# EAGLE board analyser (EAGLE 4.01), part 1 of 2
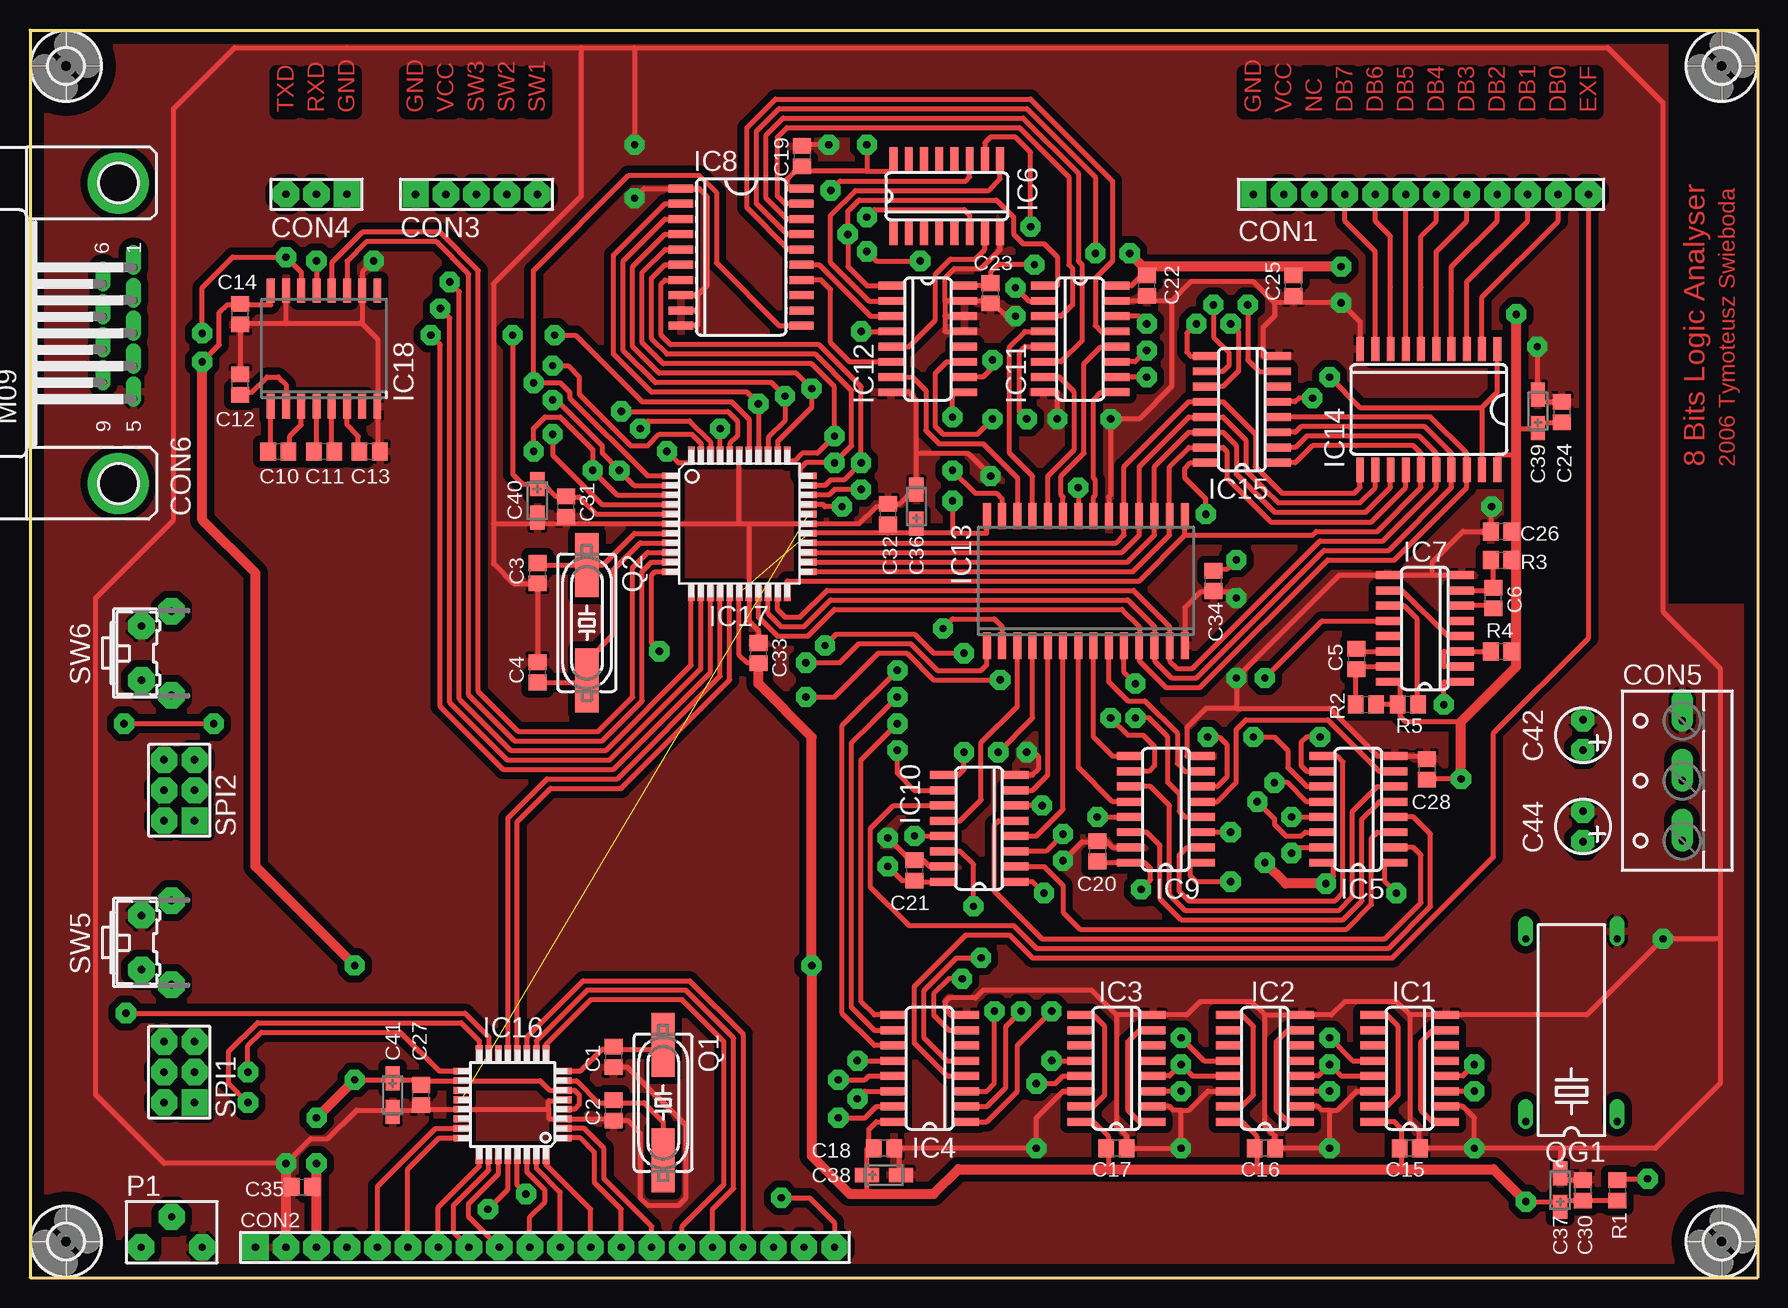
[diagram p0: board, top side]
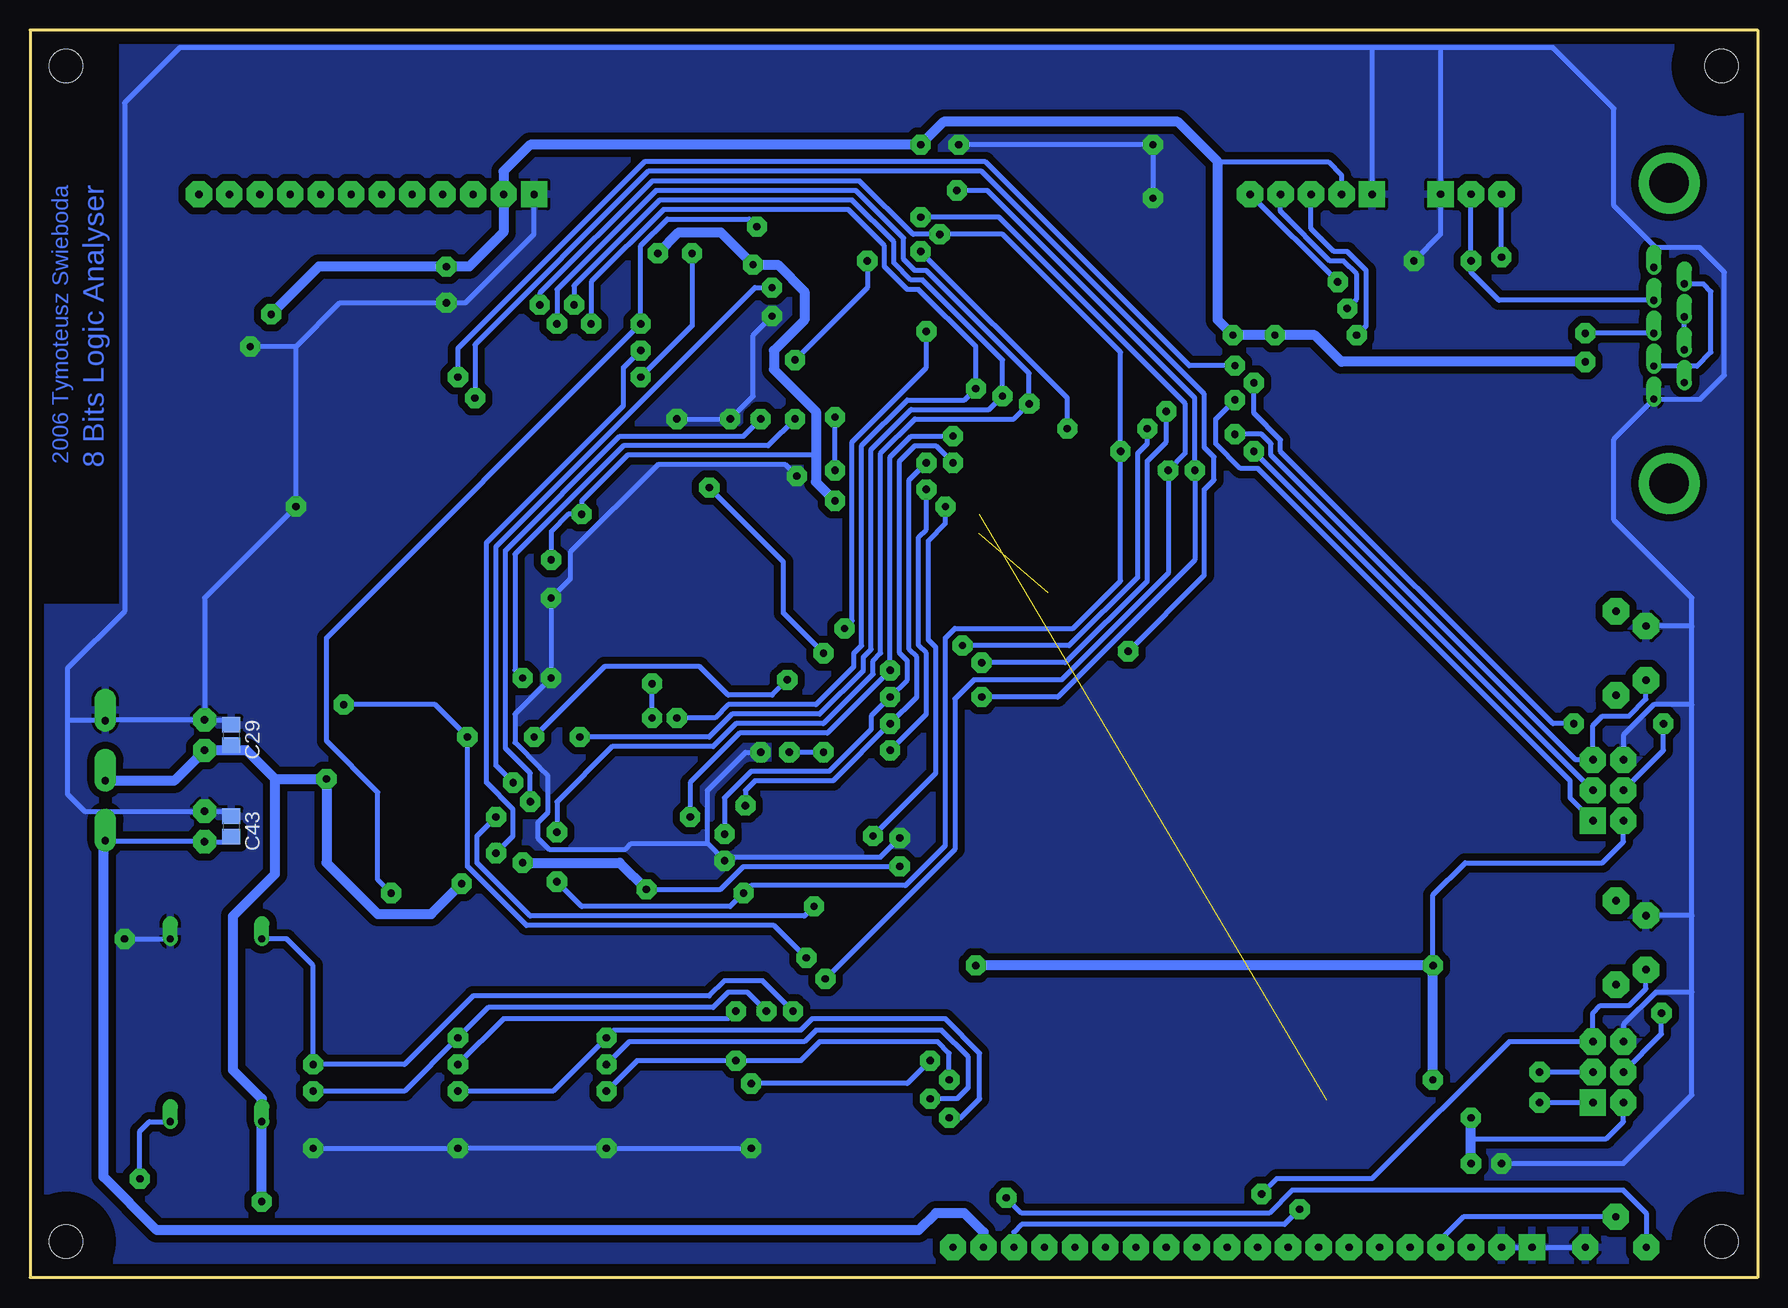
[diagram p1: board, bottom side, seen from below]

Size 144 x 104 mm. Coordinates in mm from the lower left corner, seen from the top.
Outline: 0,0 144,0 144,104 0,104 0,0
Copper layers used: Top, Bottom

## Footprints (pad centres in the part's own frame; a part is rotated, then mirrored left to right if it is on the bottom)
0805 = smd 1.3 x 1.5: 1 -0.85,0; 2 0.85,0
3216 = smd 2 x 1.2: + -1.4,0; - 1.4,0
02P100RA = drill 0.61 pad 1.93 octagon: N -1.27,0; P 1.27,0
CON12X1 = drill 0.61 pad 2.184 square: 1 0,0 | drill 0.61 pad 2.184 octagon: 2 2.54,0; 3 5.08,0; 4 7.62,0; 5 10.16,0; 6 12.7,0; 7 15.24,0; 8 17.78,0; 9 20.32,0; 10 22.86,0; 11 25.4,0; 12 27.94,0
CON20X1 = drill 0.61 pad 2.184 square: 1 0,0 | drill 0.61 pad 2.184 octagon: 2 2.54,0; 3 5.08,0; 4 7.62,0; 5 10.16,0; 6 12.7,0; 7 15.24,0; 8 17.78,0; 9 20.32,0; 10 22.86,0; 11 25.4,0; 12 27.94,0; 13 30.48,0; 14 33.02,0; 15 35.56,0; 16 38.1,0; 17 40.64,0; 18 43.18,0; 19 45.72,0; 20 48.26,0
CON05X1 = drill 0.61 pad 2.184 square: 1 0,0 | drill 0.61 pad 2.184 octagon: 2 2.54,0; 3 5.08,0; 4 7.62,0; 5 10.16,0
CON03X1 = drill 0.61 pad 2.184 square: 1 0,0 | drill 0.61 pad 2.184 octagon: 2 2.54,0; 3 5.08,0
ARK3 = drill 0.61 pad 1.778 offset: 1 0.08,-0.02; 2 5.08,-0.02; 3 10.08,-0.02
SUBD09MH = drill 0.61 pad 1.27 offset: 1 5.486,0; 2 2.743,0; 3 0,0; 4 -2.743,0; 5 -5.486,0; 6 4.115,2.54; 7 1.372,2.54; 8 -1.372,2.54; 9 -4.115,2.54 | drill 3.302 pad 5.08 round: G1 -12.522,1.27; G2 12.522,1.27
SO16 = smd 0.66 x 2.032: 1 -4.445,-3.073; 2 -3.175,-3.073; 3 -1.905,-3.073; 4 -0.635,-3.073; 5 0.635,-3.073; 6 1.905,-3.073; 7 3.175,-3.073; 8 4.445,-3.073; 9 4.445,3.073; 10 3.175,3.073; 11 1.905,3.073; 12 0.635,3.073; 13 -0.635,3.073; 14 -1.905,3.073; 15 -3.175,3.073; 16 -4.445,3.073
SO20W = smd 0.66 x 2.032: 1 -5.715,-5.029; 2 -4.445,-5.029; 3 -3.175,-5.029; 4 -1.905,-5.029; 5 -0.635,-5.029; 6 0.635,-5.029; 7 1.905,-5.029; 8 3.175,-5.029; 9 4.445,-5.029; 10 5.715,-5.029; 11 5.715,5.029; 12 4.445,5.029; 13 3.175,5.029; 14 1.905,5.029; 15 0.635,5.029; 16 -0.635,5.029; 17 -1.905,5.029; 18 -3.175,5.029; 19 -4.445,5.029; 20 -5.715,5.029
SO28X = smd 0.66 x 2.2: 1 -8.255,-5.4; 2 -6.985,-5.4; 3 -5.715,-5.4; 4 -4.445,-5.4; 5 -3.175,-5.4; 6 -1.905,-5.4; 7 -0.635,-5.4; 8 0.635,-5.4; 9 1.905,-5.4; 10 3.175,-5.4; 11 4.445,-5.4; 12 5.715,-5.4; 13 6.985,-5.4; 14 8.255,-5.4; 15 8.255,5.4; 16 6.985,5.4; 17 5.715,5.4; 18 4.445,5.4; 19 3.175,5.4; 20 1.905,5.4; 21 0.635,5.4; 22 -0.635,5.4; 23 -1.905,5.4; 24 -3.175,5.4; 25 -4.445,5.4; 26 -5.715,5.4; 27 -6.985,5.4; 28 -8.255,5.4
TQFP32 = smd 1.27 x 0.559: 1 -4.293,2.787; 2 -4.293,1.987; 3 -4.293,1.187; 4 -4.286,0.387; 5 -4.293,-0.387; 6 -4.293,-1.187; 7 -4.293,-1.987; 8 -4.293,-2.787; 17 4.293,-2.787; 18 4.293,-1.987; 19 4.293,-1.187; 20 4.293,-0.387; 21 4.293,0.387; 22 4.293,1.187; 23 4.293,1.987; 24 4.293,2.787 | smd 0.559 x 1.27: 9 -2.787,-4.293; 10 -1.987,-4.293; 11 -1.187,-4.293; 12 -0.387,-4.293; 13 0.387,-4.293; 14 1.187,-4.293; 15 1.987,-4.293; 16 2.787,-4.293; 25 2.787,4.293; 26 1.987,4.293; 27 1.187,4.293; 28 0.387,4.293; 29 -0.387,4.293; 30 -1.187,4.293; 31 -1.987,4.293; 32 -2.787,4.293
TQFP44 = smd 1.27 x 0.559: 1 -5.791,4; 2 -5.791,3.2; 3 -5.791,2.4; 4 -5.791,1.6; 5 -5.791,0.8; 6 -5.791,0; 7 -5.791,-0.8; 8 -5.791,-1.6; 9 -5.791,-2.4; 10 -5.791,-3.2; 11 -5.791,-4; 23 5.791,-4; 24 5.791,-3.2; 25 5.791,-2.4; 26 5.791,-1.6; 27 5.791,-0.8; 28 5.791,0; 29 5.791,0.8; 30 5.791,1.6; 31 5.791,2.4; 32 5.791,3.2; 33 5.791,4 | smd 0.559 x 1.27: 12 -4,-5.791; 13 -3.2,-5.791; 14 -2.4,-5.791; 15 -1.6,-5.791; 16 -0.8,-5.791; 17 0,-5.791; 18 0.8,-5.791; 19 1.6,-5.791; 20 2.4,-5.791; 21 3.2,-5.791; 22 4,-5.791; 34 4,5.791; 35 3.2,5.791; 36 2.4,5.791; 37 1.6,5.791; 38 0.8,5.791; 39 0,5.791; 40 -0.8,5.791; 41 -1.6,5.791; 42 -2.4,5.791; 43 -3.2,5.791; 44 -4,5.791
SOIC16W = smd 0.66 x 2.032: 1 -4.445,-4.825; 2 -3.175,-4.825; 3 -1.905,-4.825; 4 -0.635,-4.825; 5 0.635,-4.825; 6 1.905,-4.825; 7 3.175,-4.825; 8 4.445,-4.825; 9 4.445,4.825; 10 3.175,4.825; 11 1.905,4.825; 12 0.635,4.825; 13 -0.635,4.825; 14 -1.905,4.825; 15 -3.175,4.825; 16 -4.445,4.825
POT01 = drill 0.61 pad 2.184 octagon: 1 -2.54,-1.27; 2 2.54,-1.27; S 0,1.27
HC49S = smd 5.334 x 1.93: 1 -4.826,0; 2 4.826,0
DIL14-4 = drill 0.61 pad 1.27 offset: 1 -7.62,-3.81; 7 7.62,-3.81; 8 7.62,3.81; 14 -7.62,3.81
CON03X2 = drill 0.61 pad 2.184 square: 1 0,0 | drill 0.61 pad 2.184 octagon: 2 0,2.54; 3 2.54,0; 4 2.54,2.54; 5 5.08,0; 6 5.08,2.54
SW01V = drill 0.61 pad 2.184 octagon: 1 -2.261,2.565; 2 2.261,2.565; 3 -3.505,5.055; 4 3.505,5.055
2,8 = hole 2.8: 0,0

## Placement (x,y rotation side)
C1  22p  [0805]  48.64,18.39 270 top
C2  22p  [0805]  48.64,13.95 90 top
C3  22p  [0805]  42.29,58.71 270 top
C4  22p  [0805]  42.29,50.46 270 top
C5  22p  [0805]  110.56,51.57 270 top
C6  22p  [0805]  121.99,56.65 90 top
C10  u1  [0805]  20.7,68.87 0 top
C11  u1  [0805]  24.51,68.87 0 top
C12  u1  [0805]  17.53,74.43 90 top
C13  u1  [0805]  28.32,68.87 0 top
C14  u1  [0805]  17.53,80.3 90 top
C15  u1  [0805]  115,10.77 180 top
C16  u1  [0805]  102.94,10.77 180 top
C17  u1  [0805]  90.55,10.77 180 top
C18  u1  [0805]  71.19,10.77 180 top
C19  u1  [0805]  64.36,93.48 270 top
C20  u1  [0805]  88.97,35.54 270 top
C21  u1  [0805]  73.73,33.95 270 top
C22  u1  [0805]  93.09,82.68 90 top
C23  u1  [0805]  80.08,82.05 90 top
C24  u1  [0805]  127.69,72.14 270 top
C25  u1  [0805]  105.32,82.68 90 top
C26  u1  [0805]  122.62,62.21 0 top
C27  u1  [0805]  32.61,15.22 90 top
C28  u1  [0805]  116.43,42.36 270 top
C29  u1  [0805]  127.23,45.22 270 bottom
C30  u1  [0805]  129.45,7.28 270 top
C31  u1  [0805]  44.68,64.27 90 top
C32  u1  [0805]  71.5,63.63 270 top
C33  u1  [0805]  60.71,52.05 270 top
C34  u1  [0805]  98.65,58.08 90 top
C35  u1  [0805]  22.67,7.54 0 top
C36  10u  [3216]  73.89,64.27 90 top
C37  10u  [3216]  127.54,7.28 90 top
C38  10u  [3216]  71.19,8.55 0 top
C39  10u  [3216]  125.69,72.22 90 top
C40  10u  [3216]  42.29,64.75 270 top
C41  10u  [3216]  30.23,15.22 270 top
C42  47u  [02P100RA]  129.45,45.22 270 top
C43  u1  [0805]  127.23,37.6 270 bottom
C44  47u  [02P100RA]  129.45,37.6 270 top
CON1  [CON12X1]  101.98,90.3 0 top
CON2  [CON20X1]  18.8,2.52 0 top
CON3  [CON05X1]  32.13,90.3 0 top
CON4  [CON03X1]  26.42,90.3 180 top
CON5  [ARK3]  137.7,36.33 90 top
CON6  [SUBD09MH]  8.64,78.72 90 top
IC1  74HCT390D  [SO16]  115,17.44 90 top
IC2  74HCT390D  [SO16]  102.94,17.44 90 top
IC3  74HCT390D  [SO16]  90.55,17.44 90 top
IC4  74HCT151D  [SO16]  75,17.44 90 top
IC5  74HCT4040D  [SO16]  110.72,39.03 90 top
IC6  74HCT4040D  [SO16]  76.43,90.15 0 top
IC7  74HCT123D  [SO16]  116.27,54.11 90 top
IC8  74HCT573DW  [SO20W]  59.28,85.07 270 top
IC9  74HCT157D  [SO16]  94.68,39.03 90 top
IC10  74HCT157D  [SO16]  79.12,37.44 90 top
IC11  74HCT157D  [SO16]  87.54,78.24 270 top
IC12  74HCT157D  [SO16]  74.84,78.24 270 top
IC13  62256D  [SO28X]  88.01,58.08 0 top
IC14  74HCT541DW  [SO20W]  116.59,72.36 180 top
IC15  74HCT151D  [SO16]  101.03,72.37 90 top
IC16  MEGA8R  [TQFP32]  40.23,14.42 180 top
IC17  MEGA16R  [TQFP44]  59.12,62.84 0 top
IC18  MAX232DW  [SOIC16W]  24.51,77.45 0 top
P1  10k  [POT01]  11.81,3.79 0 top
Q1  [HC49S]  52.77,14.58 270 top
Q2  12MHz  [HC49S]  46.42,54.59 270 top
QG1  1 MHz  [DIL14-4]  128.5,20.61 90 top
R1  10k  [0805]  132.31,7.28 270 top
R2  10k  [0805]  111.35,47.76 0 top
R3  10k  [0805]  122.62,59.82 0 top
R4  10k  [0805]  122.62,52.2 0 top
R5  10k  [0805]  114.84,47.76 180 top
SPI1  SPI6  [CON03X2]  13.72,14.58 90 top
SPI2  SPI6  [CON03X2]  13.72,38.08 90 top
SW5  [SW01V]  6.73,27.92 270 top
SW6  [SW01V]  6.73,52.05 270 top
U$3  [2,8]  3,101 0 top
U$4  [2,8]  3,3 0 top
U$5  [2,8]  141,101 0 top
U$6  [2,8]  141,3 0 top

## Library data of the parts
C1-C6 C10-C44 P1 Q1 Q2 QG1 R1-R5 = discrete
CON1 CON3-CON6 = connector
CON2 = special
IC1-IC12 IC14 IC15 = 74xx
IC13 = memory
IC16 IC17 SPI1 SPI2 = atmel
IC18 = linear
SW5 SW6 = switch
U$3-U$6 = holes

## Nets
1A0: IC5.9 IC9.2
1A1: IC5.7 IC9.5
1A2: IC5.6 IC9.11
1A3: IC5.5 IC9.14
1A4: IC5.3 IC10.2
1A5: IC5.2 IC10.5
1A6: IC5.4 IC10.11
1A7: IC5.13 IC10.14
1A8: IC5.12 IC11.2
1A9: IC5.14 IC11.5
1A10: IC5.15 IC11.11
1A11: IC5.1 IC6.10 IC11.14
1A12: IC6.9 IC12.2
1A13: IC6.7 IC12.5
1C0: IC16.12 IC17.16
1C1: IC16.13 IC17.15
1D0: IC13.11 IC14.18 IC15.4 IC17.19
1D1: IC13.12 IC14.17 IC15.3 IC17.20
1D2: IC13.13 IC14.16 IC15.2 IC17.21
1D3: IC13.15 IC14.15 IC15.1 IC17.22
1D4: IC13.16 IC14.14 IC15.15 IC17.23
1D5: IC13.17 IC14.13 IC15.14 IC17.24
1D6: IC13.18 IC14.12 IC15.13 IC17.25
1D7: IC13.19 IC14.11 IC15.12 IC17.26
1G0: CON2.10 IC16.30
1G1: CON2.11 IC16.31
1G2: CON2.12 IC16.32
1G3: CON2.13 IC16.1
1G4: CON2.14 IC16.2
1G5: CON2.15 IC16.9
1G6: CON2.16 IC16.10
1G7: CON2.17 IC16.11
2A0: IC8.2 IC9.3 IC15.11 IC17.37
2A1: IC8.3 IC9.6 IC15.10 IC17.36
2A2: IC8.4 IC9.10 IC15.9 IC17.35
2A3: IC4.11 IC8.5 IC9.13 IC17.34
2A4: IC4.10 IC8.6 IC10.3 IC17.33
2A5: IC4.9 IC8.7 IC10.6 IC17.32
2A6: IC10.10 IC17.31
2A7: IC10.13 IC17.30
2A8: IC8.19 IC11.3
2A9: IC8.18 IC11.6
2A10: IC8.17 IC11.10
2A11: IC8.16 IC11.13
2A12: IC8.15 IC12.3
2A13: IC8.14 IC12.6
2D0: CON1.11 IC14.2
2D1: CON1.10 IC14.3
2D2: CON1.9 IC14.4
2D3: CON1.8 IC14.5
2D4: CON1.7 IC14.6
2D5: CON1.6 IC14.7
2D6: CON1.5 IC14.8
2D7: CON1.4 IC14.9
3A0: IC9.4 IC13.10
3A1: IC9.7 IC13.9
3A2: IC9.9 IC13.8
3A3: IC9.12 IC13.7
3A4: IC10.4 IC13.6
3A5: IC10.7 IC13.5
3A6: IC10.9 IC13.4
3A7: IC10.12 IC13.3
3A8: IC11.4 IC13.25
3A9: IC11.7 IC13.24
3A10: IC11.9 IC13.21
3A11: IC11.12 IC13.23
3A12: IC12.4 IC13.2
3A13: IC12.7 IC13.26
+5V: C43.2 C44.P CON2.19 CON5.1
AREF: IC16.20 IC17.29
CD: CON2.8 IC16.26
CE: CON2.7 IC16.25
CL: IC5.11 IC6.11 IC17.3 SPI2.3
DE: IC14.1 IC14.19 IC17.43
EXF: CON1.12 IC4.4
F1: IC3.13 IC4.12
F1K: IC2.3 IC2.12 IC4.15
F1M: IC1.4 IC4.3 QG1.8
F10: IC3.3 IC3.12 IC4.13
F10K: IC1.13 IC2.4 IC4.1
F100: IC2.13 IC3.4 IC4.14
F100K: IC1.3 IC1.12 IC4.2
FD1A: IC1.1 IC1.7
FD1B: IC1.9 IC1.15
FD2A: IC2.1 IC2.7
FD2B: IC2.9 IC2.15
FD3A: IC3.1 IC3.7
FD3B: IC3.9 IC3.15
FRQ: IC4.5 IC5.10 IC7.1
FS: CON2.18 IC16.28
GND: C1.2 C2.1 C3.2 C4.1 C12.2 C13.2 C14.1 C15.1 C16.1 C17.1 C18.1 C19.1 C20.1 C21.1 C22.1 C23.1 C24.1 C25.1 C26.1 C27.1 C28.1 C29.1 C30.1 C31.1 C32.1 C33.1 C34.1 C35.1 C36.- C37.- C38.- C39.- C40.- C41.- C42.N C43.1 C44.N CON1.1 CON2.1 CON2.2 CON3.1 CON4.1 CON5.3 CON6.5 IC1.2 IC1.8 IC1.14 IC2.2 IC2.8 IC2.14 IC3.2 IC3.8 IC3.14 IC4.8 IC5.8 IC6.8 IC7.8 IC7.9 IC8.1 IC8.8 IC8.9 IC8.10 IC9.8 IC9.15 IC10.8 IC10.15 IC11.8 IC11.15 IC12.8 IC12.13 IC12.14 IC12.15 IC13.14 IC13.20 IC14.10 IC15.8 IC16.3 IC16.5 IC16.21 IC17.6 IC17.18 IC17.28 IC17.39 IC18.8 IC18.10 IC18.15 P1.2 QG1.7 SPI1.6 SPI2.6 SW5.1 SW6.1
LE: IC8.11 IC17.1 SPI2.4
MISO: IC16.16 SPI1.1
MOSI: IC16.15 SPI1.4
N$1: C10.1 IC18.1
N$2: C10.2 IC18.3
N$3: QG1.1 R1.1
N$4: CON6.4 CON6.6
N$5: CON6.7 CON6.8
N$6: C11.1 IC18.4
N$7: C11.2 IC18.5
N$8: C1.1 IC16.8 Q1.1
N$9: C3.1 IC17.7 Q2.1
N$10: C12.1 IC18.2
N$11: C13.1 IC18.6
N$12: C4.2 IC17.8 Q2.2
N$13: C5.1 IC7.14
N$14: C6.1 IC7.6
N$15: C5.2 IC7.15 R2.1
N$16: IC7.11 R5.1
N$17: C6.2 IC7.7 R3.1
N$18: IC7.2 IC7.3 R4.1
N$19: C2.2 IC16.7 Q1.2
N$20: IC7.4 IC7.10
OE: IC13.22 IC17.42
OF: IC4.7 IC6.6 IC17.2 SPI2.1
RD: CON2.6 IC16.24
RES16: IC16.29 SPI1.5 SW5.2
RES17: IC17.4 SPI2.5 SW6.2
RIN: CON4.2 CON6.2 IC18.13
RST: CON2.9 IC16.27
RXD: IC17.9 IC18.12
SA: IC9.1 IC10.1 IC11.1 IC12.1 IC15.7 IC17.44
SCK: IC16.17 SPI1.3
SM: IC13.1 IC17.40
SW1: CON3.5 IC17.12
SW2: CON3.4 IC17.13
SW3: CON3.3 IC17.14
TOUT: CON4.3 CON6.3 IC18.14
TR: IC15.5 IC17.11
TXD: IC17.10 IC18.11
V0: CON2.4 P1.S
VCC: C14.2 C15.2 C16.2 C17.2 C18.2 C19.2 C20.2 C21.2 C22.2 C23.2 C24.2 C25.2 C26.2 C27.2 C28.2 C29.2 C30.2 C31.2 C32.2 C33.2 C34.2 C35.2 C36.+ C37.+ C38.+ C39.+ C40.+ C41.+ C42.P CON1.2 CON2.3 CON3.2 CON5.2 IC1.16 IC2.16 IC3.16 IC4.16 IC5.16 IC6.16 IC7.16 IC8.20 IC9.16 IC10.16 IC11.16 IC12.16 IC13.28 IC14.20 IC15.16 IC16.4 IC16.6 IC16.18 IC17.5 IC17.17 IC17.27 IC17.38 IC18.16 QG1.14 R1.2 R2.2 R3.2 R4.2 R5.2 SPI1.2 SPI2.2
VEE: CON2.20 P1.1
WC: IC7.12 IC12.11
WM: IC12.9 IC13.27
WP: IC12.10 IC17.41
WR: CON2.5 IC16.23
